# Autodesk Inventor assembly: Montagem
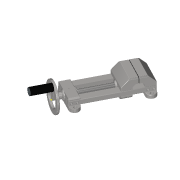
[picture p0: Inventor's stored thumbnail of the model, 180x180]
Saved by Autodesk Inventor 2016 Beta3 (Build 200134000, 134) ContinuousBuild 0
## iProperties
Created: 2016-02
Part Number: Montagem
Document SubType Name: Assembly
Designer: Vertex
Mass: 10597.2 g
Surface Area: 2647.41 cm^2
Volume: 1381.25 cm^3
Density: 7.67217 g/cm^3
Author: Vertex
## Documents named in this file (9)
- D:\My Data\Books_Final Books\Autodesk Inventor 2015_resources\Chapter 7\simple-vice\Montagem.iam
- D:\My Data\Books_Final Books\Autodesk Inventor 2015_resources\Chapter 7\simple-vice\Fixed Jaw.ipt
- D:\My Data\Books_Final Books\Autodesk Inventor 2015_resources\Chapter 7\simple-vice\Holder.ipt
- D:\My Data\Books_Final Books\Autodesk Inventor 2015_resources\Chapter 7\simple-vice\Movable_jaw.ipt
- D:\My Data\Books_Final Books\Autodesk Inventor 2015_resources\Chapter 7\simple-vice\Base_plate.ipt
- D:\My Data\Books_Final Books\Autodesk Inventor 2015_resources\Chapter 7\simple-vice\Screw.ipt
- D:\My Data\Books_Final Books\Autodesk Inventor 2015_resources\Chapter 7\simple-vice\Wheel.ipt
- D:\My Data\Books_Final Books\Autodesk Inventor 2015_resources\Chapter 7\simple-vice\Handle.ipt
- D:\My Data\Books_Final Books\Autodesk Inventor 2015_resources\Chapter 7\simple-vice\Washer.ipt
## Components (9 placed, 8 different names)
1. Holder:1 — Insert:14, Insert:15, Insert:16, Insert:26
2. Fixed Jaw:1 — Insert:17, Insert:18, Insert:19, Insert:20
3. Movable_jaw:1 — Mate:6, Mate:7, Mate:8, Mate:9, Cylindrical:1, Rotation/Translation:1
4. Base_plate:1 — Insert:15, Insert:16, Mate:7, Mate:9, Insert:17, Insert:18
5. Base_plate:2 — Insert:14, Mate:6, Mate:8, Insert:19, Insert:20
6. Screw:1 — Cylindrical:1, Mate:11, Mate:12, Rotation/Translation:1
7. Wheel:1 — Mate:11, Mate:12, Insert:23, Insert:24, Insert:26
8. Handle:1 — Insert:23
9. Washer:1 — Insert:24
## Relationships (18: Insert 10, Mate 6, CylindricalJoint 1, RelateRotateTranslate 1)
- Insert:14: Holder:1 ↔ Base_plate:2
- Insert:15: Holder:1 ↔ Base_plate:1
- Insert:16: Holder:1 ↔ Base_plate:1
- Mate:6: Movable_jaw:1 ↔ Base_plate:2
- Mate:7: Movable_jaw:1 ↔ Base_plate:1
- Mate:8: Movable_jaw:1 ↔ Base_plate:2
- Mate:9: Movable_jaw:1 ↔ Base_plate:1
- Insert:17: Fixed Jaw:1 ↔ Base_plate:1
- Insert:18: Fixed Jaw:1 ↔ Base_plate:1
- Insert:19: Fixed Jaw:1 ↔ Base_plate:2
- Insert:20: Fixed Jaw:1 ↔ Base_plate:2
- Cylindrical:1: Movable_jaw:1 ↔ Screw:1
- Mate:11: Screw:1 ↔ Wheel:1
- Mate:12: Screw:1 ↔ Wheel:1
- Insert:23: Wheel:1 ↔ Handle:1
- Insert:24: Wheel:1 ↔ Washer:1
- Rotation/Translation:1 [RelateRotateTranslate]: Movable_jaw:1 ↔ Screw:1
- Insert:26: Holder:1 ↔ Wheel:1
## Named parameters: sa_0 = -686305.37192 mm, sa_1 = 0 deg, sa_2 = 1333785.94102 mm, sa_3 = 686305.37192 mm, sa_4 = 0 deg, sa_5 = -1333785.94102 mm, sa_7 = 50000 mm
